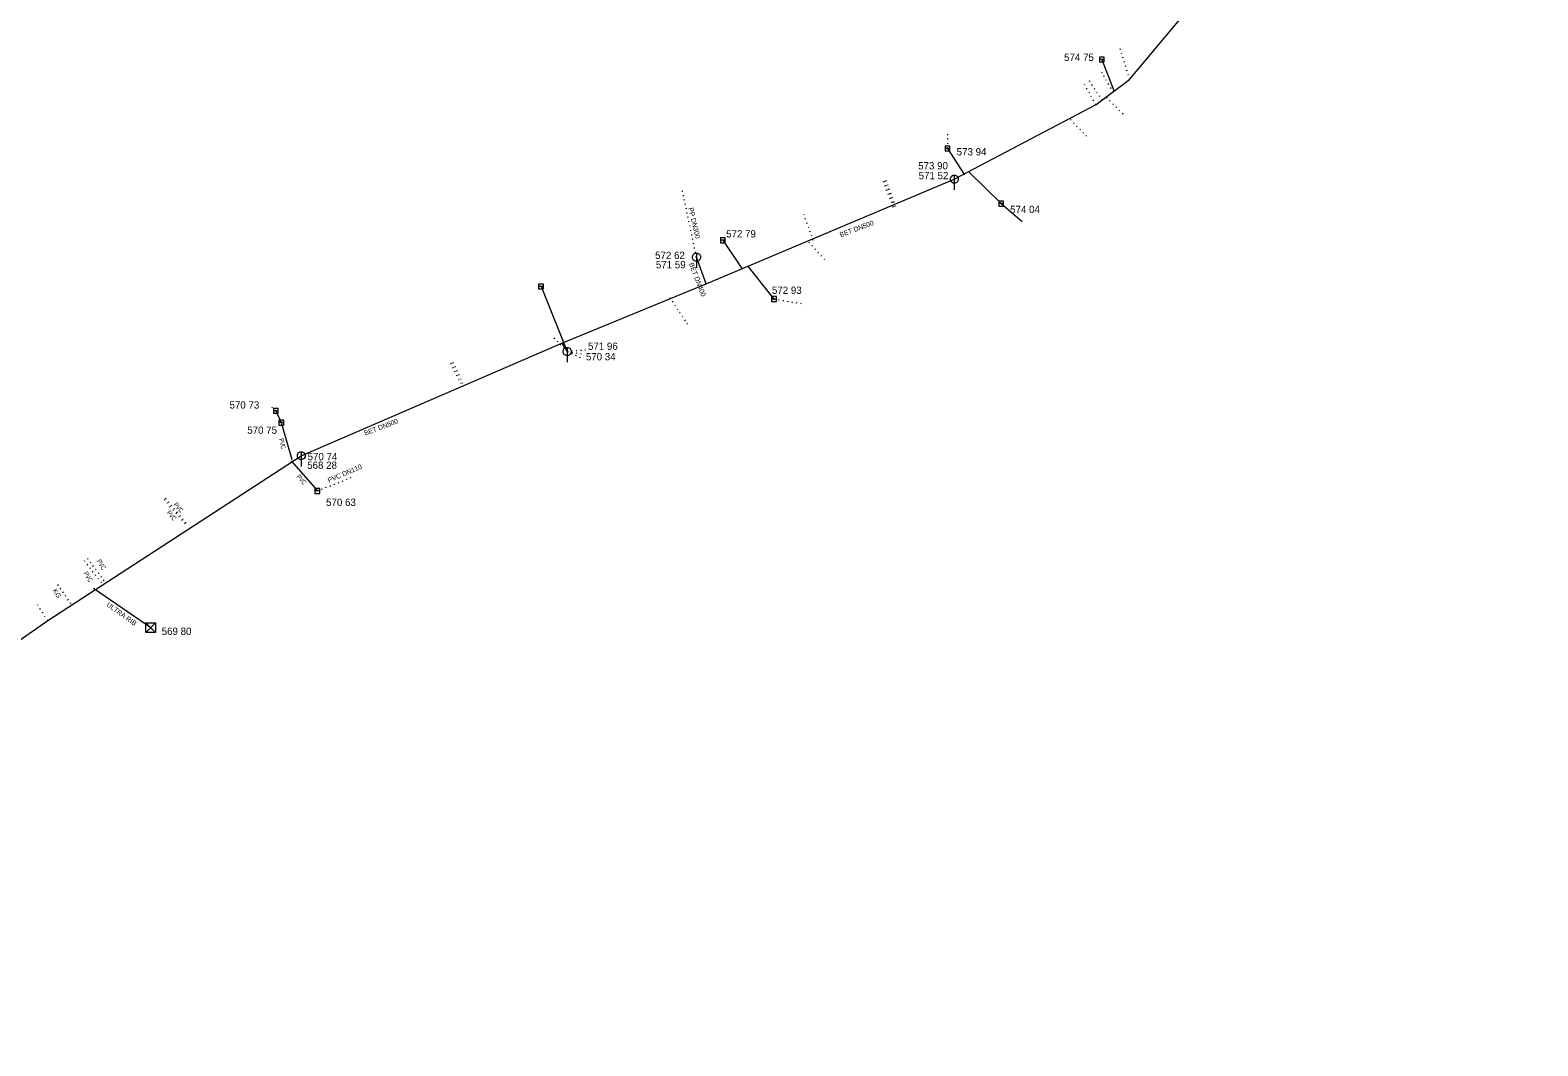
# Model space of a CAD drawing. Extents: x -710806 to -710046, y -1116920 to -1116046.
# Drawn here: x -710241.1 to -710085.7, y -1116362.9 to -1116258.1 of the extents above; entities that cross this region are included whole.
import ezdxf
from ezdxf.enums import TextEntityAlignment as Align

# ---------------------------------------------------------------- set-up
doc = ezdxf.new("R2010")
doc.units = 0
doc.header["$LTSCALE"] = 0.3
doc.linetypes.add('DOTTED', pattern=[1.5, 0.3, -1.2])
for name, color, linetype, lineweight in [('40', 7, 'Continuous', 13), ('41', 7, 'Continuous', 13), ('45', 7, 'DOTTED', 13)]:
    doc.layers.add(name, color=color, linetype=linetype, lineweight=lineweight)
doc.layers.add('43', color=7, linetype='Continuous')
doc.layers.add('44', color=7, linetype='Continuous')

msp = doc.modelspace()

# ---------------------------------------------------------------- linework, layer by layer
at = {"layer": '40', "linetype": 'DOTTED'}
msp.add_line((-710172.446, -1116281.529), (-710173.948, -1116274.429), dxfattribs=at)
at = {"layer": '40'}
for points in [[(-710171.446, -1116284.268), (-710145.874, -1116273.486), (-710131.257, -1116265.793), (-710127.793, -1116263.212), (-710120.495, -1116254.452), (-710110.653, -1116236.079), (-710102.507, -1116213.21), (-710087.53, -1116171.086), (-710085.71, -1116163.96)], [(-710186.313, -1116290.382), (-710171.446, -1116284.268), (-710172.446, -1116281.529)], [(-710298.116, -1116362.85), (-710269.531, -1116340.009), (-710239.325, -1116318.997), (-710213.195, -1116302), (-710186.313, -1116290.382), (-710185.783, -1116291.255)]]:
    msp.add_lwpolyline(points, dxfattribs=at)
at = {"layer": '41'}
for p, q in [((-710130.412, -1116260.89), (-710130.912, -1116260.89)), ((-710130.912, -1116260.89), (-710130.912, -1116261.39)), ((-710130.412, -1116261.14), (-710130.912, -1116261.14)), ((-710130.912, -1116261.39), (-710130.412, -1116261.39)), ((-710130.412, -1116261.39), (-710130.412, -1116260.89)), ((-710146.314, -1116270.068), (-710146.814, -1116270.068)), ((-710146.814, -1116270.068), (-710146.814, -1116270.568)), ((-710146.314, -1116270.318), (-710146.814, -1116270.318)), ((-710146.814, -1116270.568), (-710146.314, -1116270.568)), ((-710146.314, -1116270.568), (-710146.314, -1116270.068)), ((-710145.874, -1116273.086), (-710145.874, -1116274.586)), ((-710140.782, -1116275.757), (-710141.282, -1116275.757)), ((-710141.282, -1116275.757), (-710141.282, -1116276.257)), ((-710140.782, -1116276.007), (-710141.282, -1116276.007)), ((-710141.282, -1116276.257), (-710140.782, -1116276.257)), ((-710140.782, -1116276.257), (-710140.782, -1116275.757)), ((-710169.487, -1116279.534), (-710169.987, -1116279.534)), ((-710169.987, -1116279.534), (-710169.987, -1116280.034)), ((-710169.487, -1116279.784), (-710169.987, -1116279.784)), ((-710169.987, -1116280.034), (-710169.487, -1116280.034)), ((-710169.487, -1116280.034), (-710169.487, -1116279.534)), ((-710172.446, -1116281.129), (-710172.446, -1116282.629)), ((-710188.219, -1116284.299), (-710188.719, -1116284.299)), ((-710188.719, -1116284.299), (-710188.719, -1116284.799)), ((-710188.219, -1116284.549), (-710188.719, -1116284.549)), ((-710188.219, -1116284.799), (-710188.219, -1116284.299)), ((-710188.719, -1116284.799), (-710188.219, -1116284.799)), ((-710164.213, -1116285.595), (-710164.713, -1116285.595)), ((-710164.713, -1116285.595), (-710164.713, -1116286.095)), ((-710164.213, -1116285.845), (-710164.713, -1116285.845)), ((-710164.713, -1116286.095), (-710164.213, -1116286.095)), ((-710164.213, -1116286.095), (-710164.213, -1116285.595)), ((-710185.783, -1116290.855), (-710185.783, -1116292.355)), ((-710215.566, -1116297.119), (-710216.066, -1116297.119)), ((-710216.066, -1116297.119), (-710216.066, -1116297.619)), ((-710215.566, -1116297.619), (-710215.566, -1116297.119)), ((-710215.566, -1116297.369), (-710216.066, -1116297.369)), ((-710216.066, -1116297.619), (-710215.566, -1116297.619)), ((-710215.002, -1116298.339), (-710215.502, -1116298.339)), ((-710215.502, -1116298.339), (-710215.502, -1116298.839)), ((-710215.002, -1116298.589), (-710215.502, -1116298.589)), ((-710215.002, -1116298.839), (-710215.002, -1116298.339)), ((-710215.502, -1116298.839), (-710215.002, -1116298.839)), ((-710213.195, -1116301.6), (-710213.195, -1116303.1)), ((-710211.283, -1116305.38), (-710211.783, -1116305.38)), ((-710211.783, -1116305.38), (-710211.783, -1116305.88)), ((-710211.283, -1116305.63), (-710211.783, -1116305.63)), ((-710211.783, -1116305.88), (-710211.283, -1116305.88)), ((-710211.283, -1116305.88), (-710211.283, -1116305.38)), ((-710229.212, -1116319.215), (-710228.212, -1116320.215)), ((-710228.212, -1116319.215), (-710229.212, -1116320.215))]:
    msp.add_line(p, q, dxfattribs=at)
for points in [[(-710146.274, -1116273.586), (-710146.274, -1116273.386), (-710146.174, -1116273.186), (-710145.974, -1116273.086), (-710145.774, -1116273.086), (-710145.574, -1116273.186), (-710145.474, -1116273.386), (-710145.474, -1116273.586), (-710145.574, -1116273.786), (-710145.774, -1116273.886), (-710145.974, -1116273.886), (-710146.174, -1116273.786)], [(-710172.846, -1116281.629), (-710172.846, -1116281.429), (-710172.746, -1116281.229), (-710172.546, -1116281.129), (-710172.346, -1116281.129), (-710172.146, -1116281.229), (-710172.046, -1116281.429), (-710172.046, -1116281.629), (-710172.146, -1116281.829), (-710172.346, -1116281.929), (-710172.546, -1116281.929), (-710172.746, -1116281.829)], [(-710186.183, -1116291.355), (-710186.183, -1116291.155), (-710186.083, -1116290.955), (-710185.883, -1116290.855), (-710185.683, -1116290.855), (-710185.483, -1116290.955), (-710185.383, -1116291.155), (-710185.383, -1116291.355), (-710185.483, -1116291.555), (-710185.683, -1116291.655), (-710185.883, -1116291.655), (-710186.083, -1116291.555)], [(-710213.595, -1116302.1), (-710213.595, -1116301.9), (-710213.495, -1116301.7), (-710213.295, -1116301.6), (-710213.095, -1116301.6), (-710212.895, -1116301.7), (-710212.795, -1116301.9), (-710212.795, -1116302.1), (-710212.895, -1116302.3), (-710213.095, -1116302.4), (-710213.295, -1116302.4), (-710213.495, -1116302.3)], [(-710229.212, -1116319.215), (-710228.212, -1116319.215), (-710228.212, -1116320.215), (-710229.212, -1116320.215)]]:
    msp.add_lwpolyline(points, close=True, dxfattribs=at)
at = {"layer": '45'}
for p, q in [((-710127.793, -1116263.212), (-710128.83, -1116259.816)), ((-710129.482, -1116264.517), (-710130.705, -1116262.419)), ((-710131.257, -1116265.793), (-710132.524, -1116263.593)), ((-710130.614, -1116265.352), (-710132.14, -1116263.057)), ((-710130.184, -1116265.058), (-710128.371, -1116266.895)), ((-710133.903, -1116267.344), (-710132.041, -1116269.252)), ((-710146.564, -1116270.318), (-710146.511, -1116268.563)), ((-710152.157, -1116276.4), (-710153.273, -1116273.492)), ((-710152.029, -1116276.353), (-710153.125, -1116273.459)), ((-710151.908, -1116276.314), (-710152.968, -1116273.406)), ((-710160.411, -1116279.808), (-710161.499, -1116276.807)), ((-710160.852, -1116279.989), (-710159.035, -1116281.979)), ((-710175.202, -1116285.691), (-710173.388, -1116288.45)), ((-710164.463, -1116285.845), (-710161.444, -1116286.334)), ((-710185.783, -1116291.255), (-710187.245, -1116289.743)), ((-710196.702, -1116294.627), (-710197.763, -1116292.467)), ((-710196.521, -1116294.565), (-710197.533, -1116292.386)), ((-710185.783, -1116291.255), (-710183.902, -1116291.072)), ((-710185.783, -1116291.255), (-710184.187, -1116291.514)), ((-710185.783, -1116291.255), (-710184.421, -1116291.877)), ((-710215.816, -1116297.369), (-710216.39, -1116296.873)), ((-710211.533, -1116305.63), (-710208.059, -1116304.259)), ((-710225.163, -1116309.033), (-710227.448, -1116306.382)), ((-710225.068, -1116308.938), (-710227.419, -1116306.126)), ((-710233.795, -1116315.087), (-710235.784, -1116312.531)), ((-710233.521, -1116314.886), (-710235.428, -1116312.336)), ((-710236.934, -1116317.266), (-710238.325, -1116315.233)), ((-710239.325, -1116318.997), (-710240.591, -1116317.062))]:
    msp.add_line(p, q, dxfattribs=at)
at = {"layer": '45', "linetype": 'Continuous'}
for p, q in [((-710130.662, -1116261.14), (-710129.371, -1116264.446)), ((-710146.564, -1116270.318), (-710144.807, -1116273.029)), ((-710169.737, -1116279.784), (-710167.771, -1116282.706)), ((-710167.178, -1116282.427), (-710164.463, -1116285.845)), ((-710188.469, -1116284.549), (-710185.783, -1116291.255)), ((-710214.232, -1116302.528), (-710211.533, -1116305.63)), ((-710234.617, -1116315.667), (-710228.712, -1116319.715))]:
    msp.add_line(p, q, dxfattribs=at)
for points in [[(-710144.35, -1116272.773), (-710141.032, -1116276.007), (-710138.884, -1116277.841)], [(-710215.816, -1116297.369), (-710215.252, -1116298.589), (-710214.165, -1116302.39)]]:
    msp.add_lwpolyline(points, dxfattribs=at)

# ---------------------------------------------------------------- texts
at = {"layer": '43'}
for s, p in [('574 75 ', (-710132.8772, -1116261.298)), ('573 94 ', (-710143.9502, -1116271.036)), ('573 90 ', (-710147.9212, -1116272.477)), ('574 04 ', (-710138.4382, -1116276.977)), ('572 79 ', (-710167.7182, -1116279.497)), ('572 62 ', (-710175.0402, -1116281.714)), ('572 93 ', (-710162.9962, -1116285.31)), ('571 96 ', (-710181.9592, -1116291.082)), ('570 73 ', (-710218.9142, -1116297.139)), ('570 75 ', (-710217.0852, -1116299.738)), ('570 74 ', (-710210.8652, -1116302.465)), ('570 63 ', (-710208.9582, -1116307.182)), ('569 80 ', (-710225.9072, -1116320.478))]:
    msp.add_text(s, height=0.75, dxfattribs=at).set_placement(p, align=Align.CENTER)
for s, p in [('571 52', (-710149.547, -1116273.492)), ('571 59', (-710176.633, -1116282.675)), ('570 34', (-710183.85, -1116292.164)), ('568 28', (-710212.58, -1116303.354))]:
    msp.add_text(s, height=0.75, dxfattribs=at).set_placement(p)
at = {"layer": '44'}
for s, rotation, p in [('PP DN300', 283.5, (-710173.291, -1116276.476)), ('BET DN500', 20.7, (-710157.572, -1116279.487)), ('BET DN400', 290.7, (-710173.229, -1116282.201)), ('BET DN500', 20.7, (-710206.601, -1116299.933)), ('PVC DN110', 23.4, (-710210.335, -1116304.796)), ('ULTRA RIB', 324, (-710233.313, -1116317.455))]:
    msp.add_text(s, height=0.5, rotation=rotation, dxfattribs=at).set_placement(p)
for s, rotation, width, p in [('PVC', 284.4, 0.65, (-710215.522, -1116300.28)), ('PVC', 311.4, 0.65, (-710213.713, -1116304.204)), ('PVC', 311.4, 0.65, (-710227.111, -1116307.919)), ('PVC', 311.4, 0.65, (-710226.403, -1116307.081)), ('PVC', 302.4, 0.65, (-710234.318, -1116312.882)), ('PVC', 302.4, 0.65, (-710235.671, -1116314.149)), ('KG', 302.4, 0.9, (-710238.849, -1116315.909))]:
    msp.add_text(s, height=0.5, rotation=rotation, dxfattribs=dict(at, width=width)).set_placement(p)

doc.saveas('drawing.dxf')
